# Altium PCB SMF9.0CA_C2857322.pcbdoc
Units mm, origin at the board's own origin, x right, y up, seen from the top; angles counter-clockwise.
Board outline 16.7 x 14.71 mm, 2 copper layers (Top Layer, Bottom Layer), stack 0 mm thick; 1 components, 0 nets, 2 pads, 0 vias.
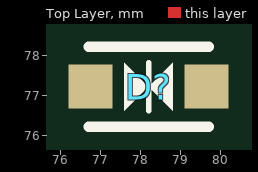
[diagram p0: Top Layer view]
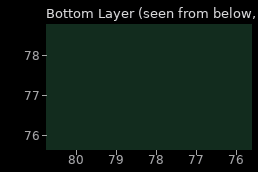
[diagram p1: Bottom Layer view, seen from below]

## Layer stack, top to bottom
Top Layer: signal copper (thickness not stored)
Bottom Layer: signal copper (thickness not stored)

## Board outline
86.551,69.85 69.85,69.85 69.85,84.56 86.551,84.56

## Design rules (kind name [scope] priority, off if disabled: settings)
PasteMaskExpansion "Paste Mask Expansion" [All] p1: expansion=0
SolderMaskExpansion "Solder Mask Expansion" [IsVia] p1: expansion=-25.4 istentingtop=TRUE
SolderMaskExpansion "Solder Mask Expansion" [All] p2: expansion=0.051 istentingtop=FALSE

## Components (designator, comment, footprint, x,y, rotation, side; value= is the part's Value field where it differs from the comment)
D? "SMF9.0CA" SMF_L2.9-W1.9-LS3.9-BI 78.2,77.21 r0 top

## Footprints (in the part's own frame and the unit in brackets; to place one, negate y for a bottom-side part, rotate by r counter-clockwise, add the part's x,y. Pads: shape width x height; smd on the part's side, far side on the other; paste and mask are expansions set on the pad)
SMF_L2.9-W1.9-LS3.9-BI [mm]
  rect 1.1x1.1 smd: 1(-1.45,0) 2(1.45,0)
  silkscreen extent -1.5,-1 1.5,1

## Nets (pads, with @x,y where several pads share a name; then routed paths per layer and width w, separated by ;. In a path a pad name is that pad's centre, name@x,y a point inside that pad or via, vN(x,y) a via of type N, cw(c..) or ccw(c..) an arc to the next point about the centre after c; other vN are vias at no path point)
pads on no net: D?.1 D?.2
